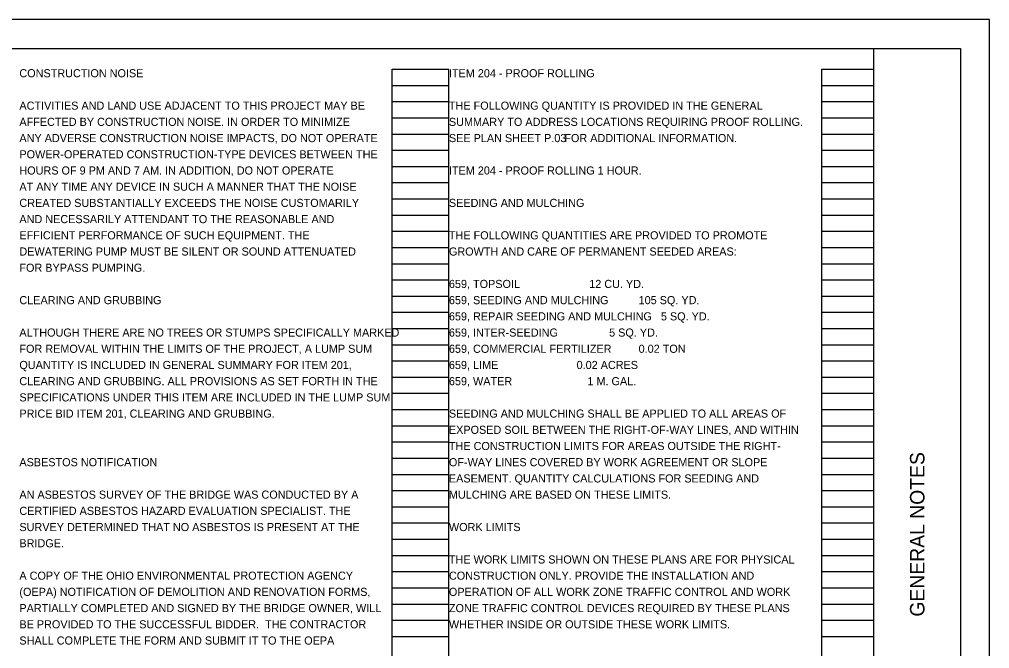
# Model space of a CAD drawing. Extents: x 0 to 84.3, y -13.4 to 22.
# Drawn here: x 17.24 to 34, y 11.13 to 22 of the extents above; entities that cross this region are included whole.
import ezdxf

# ---------------------------------------------------------------- set-up
doc = ezdxf.new("R2010")
doc.units = 0
for name, color, linetype in [('SH_Border', 7, 'Continuous'), ('SH_Cut_Line', 7, 'Continuous'), ('SH_Data', 7, 'Continuous'), ('SH_Text', 7, 'Continuous')]:
    doc.layers.add(name, color=color, linetype=linetype)

msp = doc.modelspace()

# ---------------------------------------------------------------- linework, layer by layer
at = {"layer": 'SH_Border'}
msp.add_line((32, 0.5), (32, 21.5), dxfattribs=at)
msp.add_lwpolyline([(1.5, 21.5), (33.5, 21.5), (33.5, 0.5), (1.5, 0.5)], close=True, dxfattribs=at)
at = {"layer": 'SH_Cut_Line'}
msp.add_lwpolyline([(0, 0), (34, 0), (34, 22), (0, 22)], close=True, dxfattribs=at)
at = {"layer": 'SH_Data'}
for p, q in [((23.68, 0.98), (23.68, 21.14)), ((23.68, 21.14), (24.66, 21.14)), ((24.66, 0.98), (24.66, 21.14)), ((31.1, 0.98), (31.1, 21.14)), ((31.1, 21.14), (32, 21.14)), ((32, 0.98), (32, 21.14)), ((23.68, 20.86), (24.66, 20.86)), ((31.1, 20.86), (32, 20.86)), ((23.68, 20.58), (24.66, 20.58)), ((31.1, 20.58), (32, 20.58)), ((23.68, 20.3), (24.66, 20.3)), ((31.1, 20.3), (32, 20.3)), ((23.68, 20.02), (24.66, 20.02)), ((31.1, 20.02), (32, 20.02)), ((23.68, 19.74), (24.66, 19.74)), ((31.1, 19.74), (32, 19.74)), ((23.68, 19.46), (24.66, 19.46)), ((31.1, 19.46), (32, 19.46)), ((23.68, 19.18), (24.66, 19.18)), ((31.1, 19.18), (32, 19.18)), ((23.68, 18.9), (24.66, 18.9)), ((31.1, 18.9), (32, 18.9)), ((23.68, 18.62), (24.66, 18.62)), ((31.1, 18.62), (32, 18.62)), ((23.68, 18.34), (24.66, 18.34)), ((31.1, 18.34), (32, 18.34)), ((23.68, 18.06), (24.66, 18.06)), ((31.1, 18.06), (32, 18.06)), ((23.68, 17.78), (24.66, 17.78)), ((31.1, 17.78), (32, 17.78)), ((23.68, 17.5), (24.66, 17.5)), ((31.1, 17.5), (32, 17.5)), ((23.68, 17.22), (24.66, 17.22)), ((31.1, 17.22), (32, 17.22)), ((23.68, 16.94), (24.66, 16.94)), ((31.1, 16.94), (32, 16.94)), ((23.68, 16.66), (24.66, 16.66)), ((31.1, 16.66), (32, 16.66)), ((23.68, 16.38), (24.66, 16.38)), ((31.1, 16.38), (32, 16.38)), ((23.68, 16.1), (24.66, 16.1)), ((31.1, 16.1), (32, 16.1)), ((23.68, 15.82), (24.66, 15.82)), ((31.1, 15.82), (32, 15.82)), ((23.68, 15.54), (24.66, 15.54)), ((31.1, 15.54), (32, 15.54)), ((23.68, 15.26), (24.66, 15.26)), ((31.1, 15.26), (32, 15.26)), ((23.68, 14.98), (24.66, 14.98)), ((31.1, 14.98), (32, 14.98)), ((23.68, 14.7), (24.66, 14.7)), ((31.1, 14.7), (32, 14.7)), ((23.68, 14.42), (24.66, 14.42)), ((31.1, 14.42), (32, 14.42)), ((23.68, 14.14), (24.66, 14.14)), ((31.1, 14.14), (32, 14.14)), ((23.68, 13.86), (24.66, 13.86)), ((31.1, 13.86), (32, 13.86)), ((23.68, 13.58), (24.66, 13.58)), ((31.1, 13.58), (32, 13.58)), ((23.68, 13.3), (24.66, 13.3)), ((31.1, 13.3), (32, 13.3)), ((23.68, 13.02), (24.66, 13.02)), ((31.1, 13.02), (32, 13.02)), ((23.68, 12.74), (24.66, 12.74)), ((31.1, 12.74), (32, 12.74)), ((23.68, 12.46), (24.66, 12.46)), ((31.1, 12.46), (32, 12.46)), ((23.68, 12.18), (24.66, 12.18)), ((31.1, 12.18), (32, 12.18)), ((23.68, 11.9), (24.66, 11.9)), ((31.1, 11.9), (32, 11.9)), ((23.68, 11.62), (24.66, 11.62)), ((31.1, 11.62), (32, 11.62)), ((23.68, 11.34), (24.66, 11.34)), ((31.1, 11.34), (32, 11.34))]:
    msp.add_line(p, q, dxfattribs=at)

# ---------------------------------------------------------------- texts
msp.add_text('GENERAL NOTES', height=0.25, rotation=90, dxfattribs=at).set_placement((32.875, 11.682))
at = {"layer": 'SH_Text'}
for s, p in [('CONSTRUCTION NOISE', (17.24, 21)), ('ITEM 204 - PROOF ROLLING', (24.66, 21)), ('ACTIVITIES AND LAND USE ADJACENT TO THIS PROJECT MAY BE', (17.24, 20.44)), ('THE FOLLOWING QUANTITY IS PROVIDED IN THE GENERAL', (24.66, 20.44)), ('AFFECTED BY CONSTRUCTION NOISE. IN ORDER TO MINIMIZE', (17.24, 20.16)), ('SUMMARY TO ADDRESS LOCATIONS REQUIRING PROOF ROLLING.', (24.66, 20.16)), ('ANY ADVERSE CONSTRUCTION NOISE IMPACTS, DO NOT OPERATE', (17.24, 19.88)), ('SEE PLAN SHEET P.03 ', (24.66, 19.88)), ('FOR ADDITIONAL INFORMATION.', (26.654, 19.88)), ('POWER-OPERATED CONSTRUCTION-TYPE DEVICES BETWEEN THE', (17.24, 19.6)), ('HOURS OF 9 PM AND 7 AM. IN ADDITION, DO NOT OPERATE', (17.24, 19.32)), ('ITEM 204 - PROOF ROLLING 1 HOUR.', (24.66, 19.32)), ('AT ANY TIME ANY DEVICE IN SUCH A MANNER THAT THE NOISE', (17.24, 19.04)), ('CREATED SUBSTANTIALLY EXCEEDS THE NOISE CUSTOMARILY', (17.24, 18.76)), ('SEEDING AND MULCHING', (24.66, 18.76)), ('AND NECESSARILY ATTENDANT TO THE REASONABLE AND', (17.24, 18.48)), ('EFFICIENT PERFORMANCE OF SUCH EQUIPMENT. THE ', (17.24, 18.2)), ('THE FOLLOWING QUANTITIES ARE PROVIDED TO PROMOTE', (24.66, 18.2)), ('DEWATERING PUMP MUST BE SILENT OR SOUND ATTENUATED', (17.24, 17.92)), ('GROWTH AND CARE OF PERMANENT SEEDED AREAS:', (24.66, 17.92)), ('FOR BYPASS PUMPING.', (17.24, 17.64)), ('659, TOPSOIL                       12 CU. YD.', (24.66, 17.36)), ('CLEARING AND GRUBBING', (17.24, 17.08)), ('659, SEEDING AND MULCHING          105 SQ. YD.', (24.66, 17.08)), ('659, REPAIR SEEDING AND MULCHING   5 SQ. YD.', (24.66, 16.8)), ('ALTHOUGH THERE ARE NO TREES OR STUMPS SPECIFICALLY MARKED ', (17.24, 16.52)), ('659, INTER-SEEDING                 5 SQ. YD.', (24.66, 16.52)), ('FOR REMOVAL WITHIN THE LIMITS OF THE PROJECT, A LUMP SUM ', (17.24, 16.24)), ('659, COMMERCIAL FERTILIZER         0.02 TON', (24.66, 16.24)), ('QUANTITY IS INCLUDED IN GENERAL SUMMARY FOR ITEM 201,', (17.24, 15.96)), ('659, LIME                          0.02 ACRES', (24.66, 15.96)), ('CLEARING AND GRUBBING. ALL PROVISIONS AS SET FORTH IN THE ', (17.24, 15.68)), ('659, WATER                         1 M. GAL.', (24.66, 15.68)), ('SPECIFICATIONS UNDER THIS ITEM ARE INCLUDED IN THE LUMP SUM', (17.24, 15.4)), ('PRICE BID ITEM 201, CLEARING AND GRUBBING.', (17.24, 15.12)), ('SEEDING AND MULCHING SHALL BE APPLIED TO ALL AREAS OF', (24.66, 15.12)), ('EXPOSED SOIL BETWEEN THE RIGHT-OF-WAY LINES, AND WITHIN', (24.66, 14.84)), ('THE CONSTRUCTION LIMITS FOR AREAS OUTSIDE THE RIGHT-', (24.66, 14.56)), ('ASBESTOS NOTIFICATION', (17.24, 14.28)), ('OF-WAY LINES COVERED BY WORK AGREEMENT OR SLOPE', (24.66, 14.28)), ('EASEMENT. QUANTITY CALCULATIONS FOR SEEDING AND', (24.66, 14)), ('AN ASBESTOS SURVEY OF THE BRIDGE WAS CONDUCTED BY A', (17.24, 13.72)), ('MULCHING ARE BASED ON THESE LIMITS.', (24.66, 13.72)), ('CERTIFIED ASBESTOS HAZARD EVALUATION SPECIALIST. THE', (17.24, 13.44)), ('SURVEY DETERMINED THAT NO ASBESTOS IS PRESENT AT THE', (17.24, 13.16)), ('WORK LIMITS', (24.66, 13.16)), ('BRIDGE.', (17.24, 12.88)), ('THE WORK LIMITS SHOWN ON THESE PLANS ARE FOR PHYSICAL', (24.66, 12.6)), ('A COPY OF THE OHIO ENVIRONMENTAL PROTECTION AGENCY', (17.24, 12.32)), ('CONSTRUCTION ONLY. PROVIDE THE INSTALLATION AND', (24.66, 12.32)), ('(OEPA) NOTIFICATION OF DEMOLITION AND RENOVATION FORMS,', (17.24, 12.04)), ('OPERATION OF ALL WORK ZONE TRAFFIC CONTROL AND WORK', (24.66, 12.04)), ('PARTIALLY COMPLETED AND SIGNED BY THE BRIDGE OWNER, WILL', (17.24, 11.76)), ('ZONE TRAFFIC CONTROL DEVICES REQUIRED BY THESE PLANS', (24.66, 11.76)), ('BE PROVIDED TO THE SUCCESSFUL BIDDER.  THE CONTRACTOR', (17.24, 11.48)), ('WHETHER INSIDE OR OUTSIDE THESE WORK LIMITS.', (24.66, 11.48)), ('SHALL COMPLETE THE FORM AND SUBMIT IT TO THE OEPA', (17.24, 11.2))]:
    msp.add_text(s, height=0.14, dxfattribs=at).set_placement(p)

doc.saveas('drawing.dxf')
